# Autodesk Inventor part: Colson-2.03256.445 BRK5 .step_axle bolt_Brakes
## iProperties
Created: 2010-10
Part Number: Colson-2.03256.445 BRK5 .step_axle bolt_Brakes
Document SubType Name: Modeling
Designer: Administrator
Density: 7.85 g/cm^3
Material: Steel
Mass: 36.0236 g
Surface Area: 26.8767 cm^2
Volume: 4.589 cm^3
Author: Administrator
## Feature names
1. Base1
